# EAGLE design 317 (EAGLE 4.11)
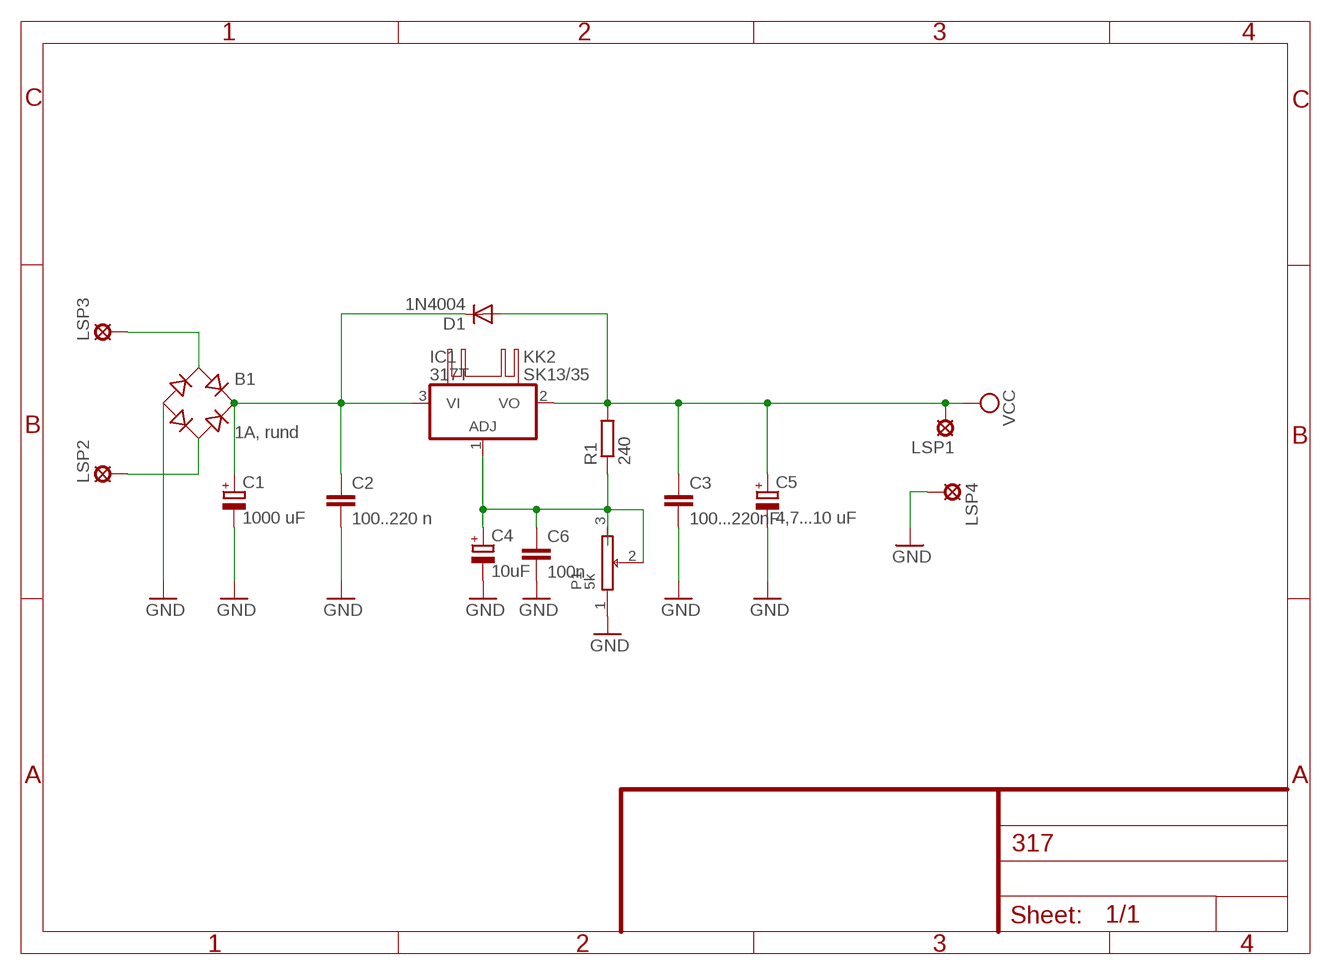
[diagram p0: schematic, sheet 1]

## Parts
B1  1A, rund  RB1A  [RB1A]
C1  1000 uF  CPOL-EUE5-13  [E5-13]
C2  100..220 n  C-EU050-030X075  [C050-030X075]
C3  100...220nF  C-EU050-030X075  [C050-030X075]
C4  10uF  CPOL-EUE2.5-7  [E2,5-7]
C5  4,7...10 uF  CPOL-EUE2.5-7  [E2,5-7]
C6  100n  C-EU050-030X075  [C050-030X075]
D1  1N4004  [DO41-10]
IC1  317T  [TO220H]
KK2  SK13/35  [SK13/35]
LSP1  SE14  [SE14]
LSP2  SE14  [SE14]
LSP3  SE14  [SE14]
LSP4  SE14  [SE14]
P1  5k  POTF_1A  [POTF_1A]
R1  240  R-EU_0207/10  [0207/10]

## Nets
GND: B1.- C1.- C2.2 C3.2 C4.- C5.- C6.2 LSP4.MP P1.1
N$1: B1.+ C1.+ C2.1 D1.C IC1.3(VI)
N$2: B1.AC1 LSP3.MP
N$3: C4.+ C6.1 IC1.1(ADJ) P1.2 P1.3 R1.1
N$4: B1.AC2 LSP2.MP
VCC: C3.1 C5.+ D1.A IC1.2(VO) LSP1.MP R1.2

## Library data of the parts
B1 = rectifier:RB1A: RECTIFIER 1 A
C1 C4 C5 = rcl:CPOL-EU: POLARIZED CAPACITOR, European symbol
C2 C3 C6 = rcl:C-EU: CAPACITOR, European symbol
D1 = diode:1N4004: DIODE
IC1 = linear:*317: Positive VOLTAGE REGULATOR
KK2 = heatsink:SK13/35: HEATSINK
LSP1-LSP4 = solpad:SE14: SOLDER PAD
P1 = Potis:POTF_1A
R1 = rcl:R-EU_: RESISTOR, European symbol

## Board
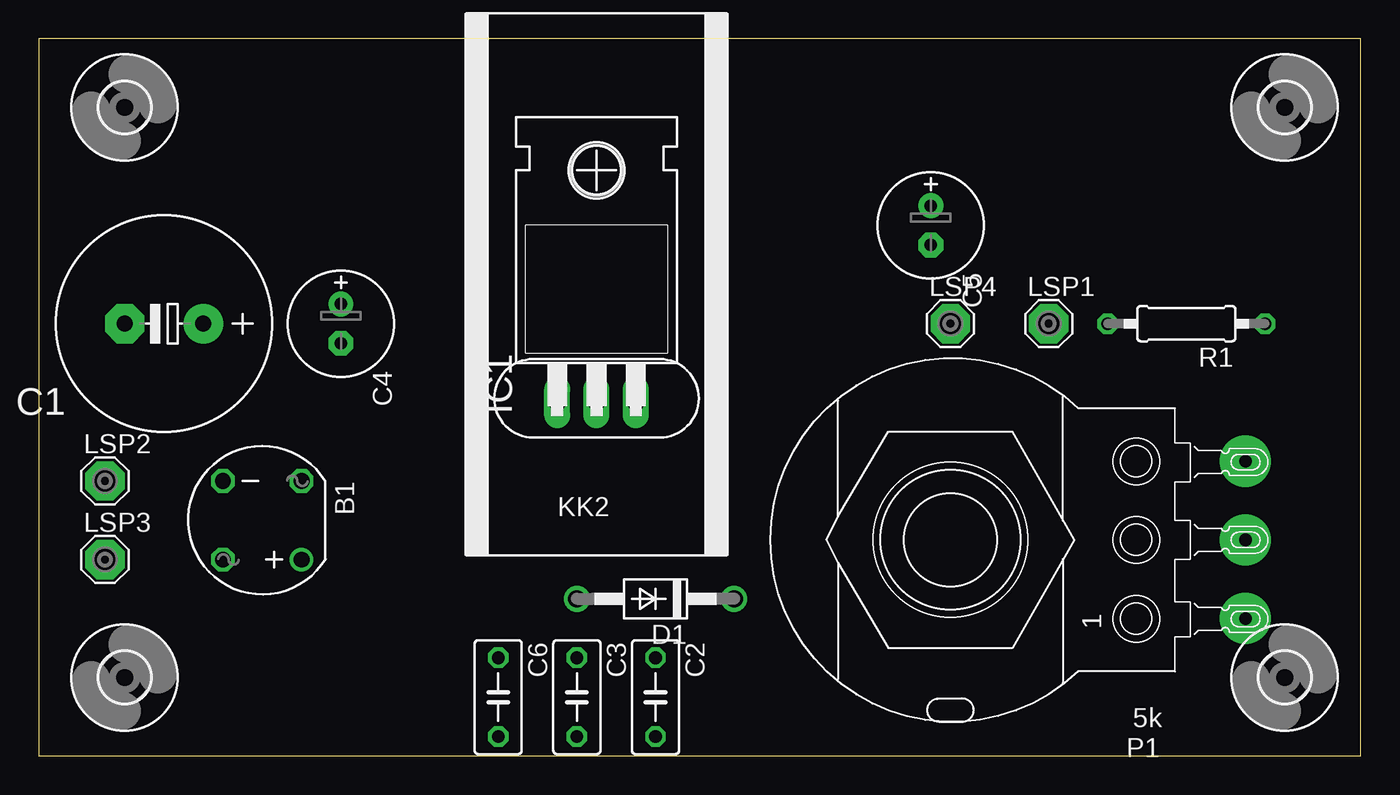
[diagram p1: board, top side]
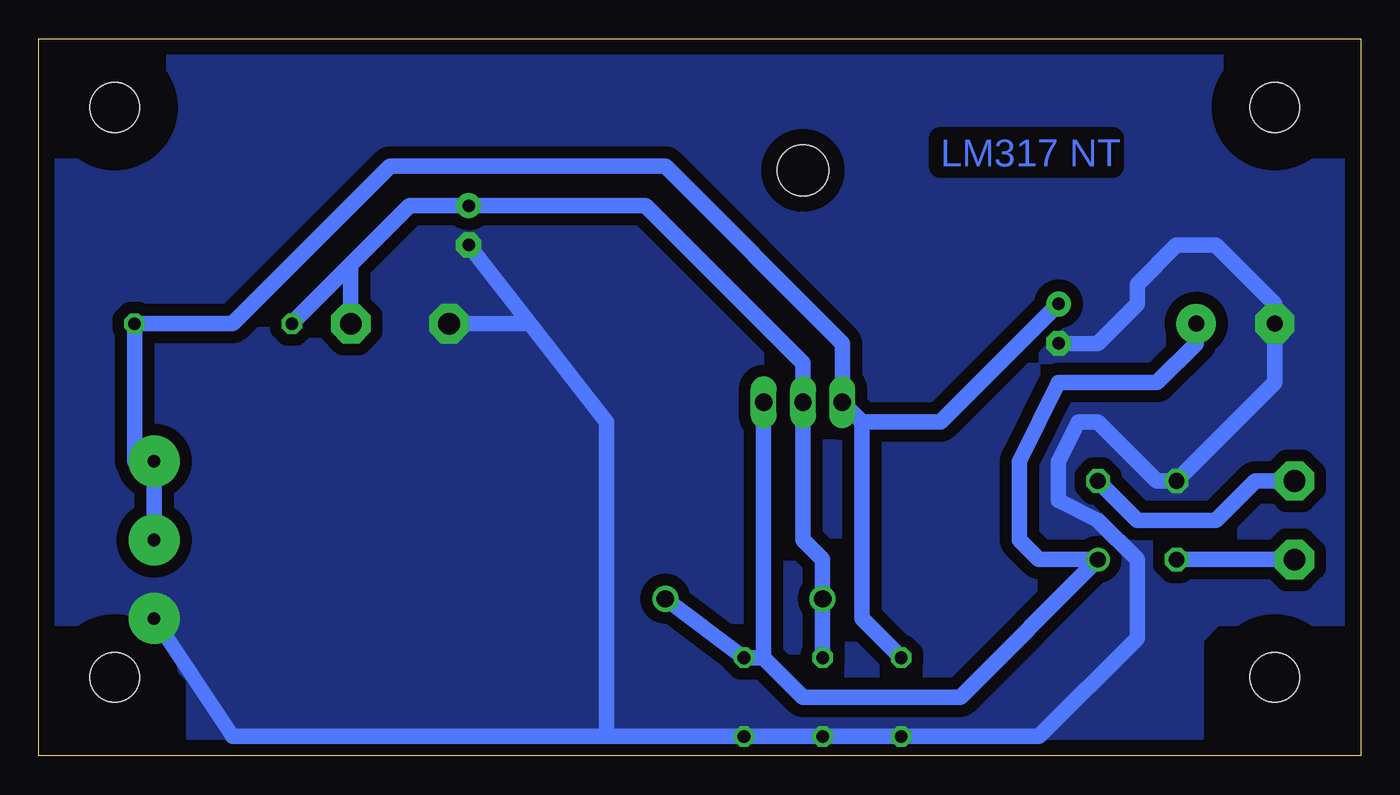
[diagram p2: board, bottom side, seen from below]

Size 85.39 x 46.34 mm. Coordinates in mm from the lower left corner, seen from the top.
Outline: 0,0 85.39,0 85.39,46.34 0,46.34 0,0
Copper layers (1*16): Top 0.035mm / dielectric 1.5mm / Bottom 0.035mm
Design rules "default": minimum track width 10mil, minimum drill 24mil, track to track 30mil, track to pad 30mil, pad to pad 18mil, via to via 18mil, smd to smd 18mil, copper to edge 40mil, drill to drill 8mil, minimum pad ring 10mil, minimum via ring 8mil, stop-mask expansion 4mil, vias tented up to drill 0mil, thermal gap 10mil

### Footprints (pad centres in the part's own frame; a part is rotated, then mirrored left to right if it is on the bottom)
RB1A = drill 1.016 round: + -2.54,2.54 | drill 1.016 octagon: - 2.54,-2.54; AC1 2.54,2.54; AC2 -2.54,-2.54
E5-13 = drill 1.016 pad 2.54 round: + -2.54,0 | drill 1.016 pad 2.54 octagon: - 2.54,0
C050-030X075 = drill 0.813 octagon: 1 -2.54,0; 2 2.54,0
E2,5-7 = drill 0.813 pad 1.6 round: + -1.27,0 | drill 0.813 pad 1.6 octagon: - 1.27,0
DO41-10 = drill 1.118 round: A 5.08,0; C -5.08,0
TO220H = drill 1.118 long: 1 -2.54,-10.16; 2 0,-10.16; 3 2.54,-10.16 | hole 3.302: 0,4.826
SE14 = drill 1.397 pad 2.54 octagon: MP 0,0
POTF_1A = drill 0.813 pad 3.302 round: 1 -5.08,-19.05; 2 0,-19.05; 3 5.08,-19.05
0207/10 = drill 0.813 octagon: 1 -5.08,0; 2 5.08,0
3,2 = hole 3.2: 0,0

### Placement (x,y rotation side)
B1  14.44,15.23 180 top
C1  8.09,27.94 180 top
C2  39.84,3.81 270 top
C3  34.76,3.81 270 top
C4  19.52,27.94 270 top
C5  57.62,34.28 270 top
C6  29.68,3.81 270 top
D1  39.84,10.15 180 top
IC1  36.03,33.02 0 top
KK2  36.03,26.67 270 top
LSP1  65.24,27.94 0 top
LSP2  4.28,17.78 0 top
LSP3  4.28,12.69 0 top
LSP4  58.89,27.94 0 top
P1  58.89,13.96 90 top
R1  74.13,27.94 180 top
U$1  [3,2]  5.55,5.08 0 top
U$3  [3,2]  5.55,41.9 0 top
U$4  [3,2]  80.48,41.9 0 top
U$5  [3,2]  80.48,5.08 0 top

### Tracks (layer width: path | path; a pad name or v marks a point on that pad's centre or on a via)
GND
  Bottom 1.016: C4.- 16.98,26.67 14.44,29.21 14.44,30.48 11.9,33.02 9.36,33.02 5.55,29.21 C1.- 5.55,24.12 B1.- 13.17,17.78 16.98,21.59 18.25,21.59 19.52,19.05 19.52,16.51 16.98,15.23 14.44,12.69 14.44,7.62 20.79,1.27 C6.2 C3.2 C2.2 48.73,1.27 | 48.73,1.27 72.86,1.27 P1.1 | 53.72,28 48.73,21.59 48.73,1.27 | 53.72,28 C5.- | 53.72,28 53.81,27.94 LSP4.MP
  pour Bottom (no thermals): 20.79,1.27 10.63,1.27 10.63,7.62 9.36,8.88 0.47,8.88 0.47,38.09 8.09,38.09 9.36,39.36 9.36,45.71 76.67,45.71 76.67,40.63 79.21,38.09 85.56,38.09 85.56,8.88 79.21,8.88 75.4,5.08 75.4,1.27 10.63,1.27
N$1
  Bottom 1.016: 38.57,6.34 IC1.3 | 38.57,6.34 C2.1 D1.C | 38.57,6.34 36.03,3.81 25.87,3.81 B1.+ 20.79,12.69 22.06,13.96 22.06,19.05 19.52,24.12 13.17,24.12 10.63,26.67 C1.+
N$2
  Bottom 1.016: LSP3.MP B1.AC1
N$3
  Bottom 1.016: C6.1 32.22,8.88 32.22,21.59 | 32.22,21.59 IC1.1 33.49,26.67 44.92,38.09 62.7,38.09 72.86,27.94 R1.1 79.21,19.05 P1.3 P1.2 | C4.+ 27.14,21.59 32.22,21.59
N$4
  Bottom 1.016: LSP2.MP 6.82,17.78 9.36,15.23 14.44,15.23 B1.AC2
VCC
  Bottom 1.016: 65.24,31.75 61.43,35.55 C5.+ 46.19,35.55 36.03,25.39 IC1.2 36.03,13.96 34.76,12.69 D1.A C3.1 | 65.24,31.75 R1.2 | 65.24,31.75 LSP1.MP

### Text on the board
Bottom: LM317 NT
